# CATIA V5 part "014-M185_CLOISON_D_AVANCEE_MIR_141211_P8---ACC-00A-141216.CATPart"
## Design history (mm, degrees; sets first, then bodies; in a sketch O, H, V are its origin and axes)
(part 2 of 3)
    Fillet35: radius 8, on edge [face of Offset41 | face of Offset41]
    Fillet36: radius 10, on edge [face of Extrude1 from Sketch2.L1 | face of Extrude1 from Sketch2.L2]
    Sweep46: type Segment, GuideCrv edge of Sweep24, GuideSurf Sweep24, Length1 33, Length2 1, Angle 5
    Sweep47: type Segment, GuideCrv edge of Sweep28, GuideSurf Sweep28, Length1 33, Length2 1, Angle 5
    Offset42: Offset Sweep47, Length 2
    Offset43: Offset Sweep46, Length 0.01
  Set8 "RAD"
    Fillet37: radius 5, on edge [face of Chamfer3 | face of Sweep60]
    FaceFillet2: ConicRatio 0.5, Face1 face of Chamfer3, Face2 face of Offset78, Radius 10
    Fillet38: radius 5, on edge [face of Sweep63 | face of Sweep77]; edge [face of Offset78 | face of Sweep63]; edge [face of Sweep76 | face of Sweep77]
    Fillet39: radius 5, on edge [face of Sweep76 | face of Sweep51]
    Fillet40: radius 5, on edge [face of Sweep51 | face of Sweep75]; edge [face of Sweep78 | face of Sweep75]; edge [face of Sweep70 | face of Sweep69]; edge [face of Sweep71 | face of Sweep70]
    Fillet41: radius 5, on edge [face of Sweep48 | face of Sweep49]
    Fillet42: radius 50, on edge [face of Sweep49 | face of Chamfer2]
    Fillet43: radius 20, on edge [face of Chamfer2 | face of Sweep50]
    Fillet44: radius 5, on edge [face of Sweep50 | face of Sweep83]
    Fillet45: radius 5, on edge [face of Sweep82 | face of Sweep83]
    Fillet46: radius 5, on edge [face of Sweep82 | face of Offset76]; edge [face of Sweep81 | face of Offset76]
    Fillet47: radius 5, on edge [face of Sweep58 | face of Sweep73]
    Fillet48: radius 5, on edge [face of Sweep59 | face of Sweep58]; edge [face of Offset63 | face of Sweep59]
    Fillet49: radius 5, on edge [face of Offset63 | face of Sweep66]; edge [face of Sweep80 | face of Sweep66]; edge [face of Sweep80 | face of Sweep68]
    Fillet50: radius 10, on edge [face of Sweep68 | face of Sweep67]
    Fillet51: radius 3, on edge [face of Sweep44 | face of Offset39]
  Set9 "LIMITS HARD"
    Offset44: Offset DatumSurface46, Length 10
    Intersect11: ToIntersect1 Extrapol167, ToIntersect2 Extrapol166
    CurvePar6: Offset Intersect11, Support Extrapol166, Offset2 0, Offset1 16
    Intersect12: ToIntersect1 DatumSurface26, ToIntersect2 DatumSurface27
    Extrapol166: ToExtrapol edge of DatumSurface27, Support DatumSurface27, Length 60
    CurvePar7: Offset Intersect12, Support Extrapol166, Offset2 0, Offset1 25
    Extrapol167: ToExtrapol edge of DatumSurface37, Support DatumSurface37, Length 60
    Intersect13: ToIntersect1 Extrapol166, ToIntersect2 DatumSurface28
    CurvePar8: Offset Intersect13, Support Extrapol166, Offset2 0, Offset1 51.5
    Offset45: Offset DatumSurface1, Length 10
    Intersect14: ToIntersect1 Offset45, ToIntersect2 Extrapol218
    Point1: type OnCurve, Support Intersect14, Ratio 0.2
    CurvePar9: Offset edge of DatumSurface34, Support Extrapol218, Offset2 0, Offset1 50, PassingPoint Point1
    CurvePar10: Offset CurvePar9, Support Extrapol218, Offset2 0, Offset1 0.5
    Sweep48: type Segment, GuideCrv CurvePar8, Length1 20, Length2 20, Angle 3, DraftDirection Line1
    Sweep49: type Segment, GuideCrv CurvePar6, Length1 20, Length2 20, Angle 3, DraftDirection Line1
    Sweep50: type Segment, GuideCrv CurvePar7, Length1 20, Length2 20, Angle 3, DraftDirection Line1
    Sweep51: type Segment, GuideCrv CurvePar10, Length1 20, Length2 20, Angle 3, DraftDirection Line1
    MultiExtract56: ListOfMultiExtractConstraints MultiExtractConstraint face of DatumSurface2
    StUntrimFeature30 "CATStUntrimFeatureName": SpecToUntrim MultiExtract56
    Offset46: Offset StUntrimFeature30, Length 4.5
    Offset47: Offset Offset46, Length 10
    MultiExtract57: ListOfMultiExtractConstraints MultiExtractConstraint face of DatumSurface2
    MultiExtract58: ListOfMultiExtractConstraints MultiExtractConstraint face of DatumSurface2
    MultiExtract59: ListOfMultiExtractConstraints MultiExtractConstraint face of DatumSurface2
    MultiExtract60: ListOfMultiExtractConstraints MultiExtractConstraint face of DatumSurface2
    StUntrimFeature31 "CATStUntrimFeatureName": SpecToUntrim MultiExtract58
    Extrapol168: ToExtrapol edge of StUntrimFeature31, Support StUntrimFeature31, Length 30
    StUntrimFeature32 "CATStUntrimFeatureName": SpecToUntrim MultiExtract57
    Extrapol169: ToExtrapol edge of StUntrimFeature32, Support StUntrimFeature32, Length 30
    Intersect15: ToIntersect1 Extrapol168, ToIntersect2 Extrapol217
    Intersect16: ToIntersect1 Extrapol169, ToIntersect2 Extrapol217
    StUntrimFeature33 "CATStUntrimFeatureName": SpecToUntrim MultiExtract59
    Extrapol170: ToExtrapol edge of StUntrimFeature33, Support StUntrimFeature33, Length 30
    Offset48: Offset Extrapol170, Length 10
    Intersect17: ToIntersect1 Offset48, ToIntersect2 Extrapol211
    StUntrimFeature34 "CATStUntrimFeatureName": SpecToUntrim MultiExtract60
    Extrapol171: ToExtrapol edge of StUntrimFeature34, Support StUntrimFeature34, Length 30
    Offset49: Offset Extrapol171, Length 10
    Intersect18: ToIntersect1 Offset49, ToIntersect2 Extrapol211
    Sweep52: type Segment, GuideCrv Intersect16, Length1 30, Length2 20, Angle 3, DraftDirection Line1
    Sweep53: type Segment, GuideCrv Intersect15, Length1 30, Length2 20, Angle 3, DraftDirection Line1
    Trim61: Trimmed (Offset57; Offset56)
    Extrapol172: ToExtrapol edge of Offset56, Support Trim61, Length 30
    Trim62: Trimmed (Sweep48; Sweep49)
    Trim63: Trimmed (Trim62; Sweep50)
    Sweep54: type Segment, GuideCrv Intersect17, Length1 30, Length2 20, Angle 3, DraftDirection Line1
    Sweep55: type Segment, GuideCrv Intersect18, Length1 30, Length2 20, Angle 3, DraftDirection Line1
    Trim64: Trimmed (Sweep54; Sweep55)
    MultiExtract61: ListOfMultiExtractConstraints MultiExtractConstraint face of DatumSurface2
    StUntrimFeature35 "CATStUntrimFeatureName": SpecToUntrim MultiExtract61
    Extrapol173: ToExtrapol edge of StUntrimFeature35, Support StUntrimFeature35, Length 30
    Offset50: Offset Extrapol173, Length 10
    Extrapol174: ToExtrapol edge of Offset47, Support Offset47, Length 30
    Intersect19: ToIntersect1 Extrapol174, ToIntersect2 Extrapol211
    Intersect20: ToIntersect1 Offset50, ToIntersect2 Extrapol211
    Sweep56: type Segment, GuideCrv Intersect19, Length1 30, Length2 20, Angle 3, DraftDirection Line1
    Sweep57: type Segment, GuideCrv Intersect20, Length1 30, Length2 20, Angle 3, DraftDirection Line1
    Trim65: Trimmed (Sweep57; Trim64)
    Trim66: Trimmed (Sweep56; Extrapol172)
    Trim67: Trimmed (Trim66; Trim65)
    MultiExtract62: ListOfMultiExtractConstraints MultiExtractConstraint face of DatumSurface3
    StUntrimFeature36 "CATStUntrimFeatureName": SpecToUntrim MultiExtract62
    Extrapol175: ToExtrapol edge of StUntrimFeature36, Support StUntrimFeature36, Length 30
    Offset51: Offset Extrapol175, Length 10
    Intersect21: ToIntersect1 Offset51, ToIntersect2 DatumSurface25
    Sweep58: type Segment, GuideCrv Intersect21, Length1 30, Length2 20, Angle 3, DraftDirection Line1
    Extrapol176: ToExtrapol edge of Sweep58, Support Sweep58, Length 50
    Extrapol177: ToExtrapol edge of Sweep58, Support Extrapol176, Length 20
    MultiExtract63: ListOfMultiExtractConstraints MultiExtractConstraint face of DatumSurface5
    StUntrimFeature37 "CATStUntrimFeatureName": SpecToUntrim MultiExtract63
    Extrapol178: ToExtrapol edge of StUntrimFeature37, Support StUntrimFeature37, Length 20
    Offset52: Offset Extrapol178, Length 10
    Intersect22: ToIntersect1 Offset52, ToIntersect2 Extrapol225
    Sweep59: type Segment, GuideCrv Intersect22, Length1 30, Length2 20, Angle 3, DraftDirection Line1
    Trim68: Trimmed (Extrapol177; Sweep59)
    MultiExtract64: ListOfMultiExtractConstraints MultiExtractConstraint face of DatumSurface6
    MultiExtract65: ListOfMultiExtractConstraints MultiExtractConstraint face of DatumSurface6
    StUntrimFeature38 "CATStUntrimFeatureName": SpecToUntrim MultiExtract64
    Extrapol179: ToExtrapol edge of StUntrimFeature38, Support StUntrimFeature38, Length 30
    StUntrimFeature39 "CATStUntrimFeatureName": SpecToUntrim MultiExtract65
    Extrapol180: ToExtrapol edge of StUntrimFeature39, Support StUntrimFeature39, Length 30
    Offset53: Offset Extrapol180, Length 10
    Offset54: Offset Extrapol179, Length 12
    Intersect23: ToIntersect1 Offset54, ToIntersect2 Extrapol217
    Intersect24: ToIntersect1 Offset53, ToIntersect2 Extrapol217
    Sweep60: type Segment, GuideCrv Intersect23, Length1 30, Length2 20, Angle 3, DraftDirection Line1
    Sweep61: type Segment, GuideCrv Intersect24, Length1 30, Length2 20, Angle 3, DraftDirection Line1
    Intersect25: ToIntersect1 Sweep60, ToIntersect2 Sweep61
    Sweep62: type Segment, GuideCrv Intersect25, GuideSurf Sweep61, Length1 30, Length2 20, Angle 3
    Offset55: Offset Sweep62, Length 0.5
    Trim69: Trimmed (Sweep60; Offset55)
    Trim70: Trimmed (Trim67; Trim69)
    Extrapol181: ToExtrapol edge of Offset55, Support Trim70, Length 50
    MultiExtract66: ListOfMultiExtractConstraints MultiExtractConstraint face of DatumSurface6
    MultiExtract67: ListOfMultiExtractConstraints MultiExtractConstraint face of DatumSurface6
    MultiExtract68: ListOfMultiExtractConstraints MultiExtractConstraint face of DatumSurface1
    StUntrimFeature40 "CATStUntrimFeatureName": SpecToUntrim MultiExtract68
    Split60: ToCut StUntrimFeature40, Cutting edge of DatumSurface1
    Split61: ToCut StUntrimFeature40, Cutting edge of Split60
    MultiExtract69: ListOfMultiExtractConstraints MultiExtractConstraint edge of Split60
    Intersect26: ToIntersect1 MultiExtract69, ToIntersect2 Extrapol217
    CurvePar11: Offset edge of DatumSurface30, Support Extrapol217, Offset2 0, Offset1 0.5, PassingPoint Intersect26
    CurvePar12: Offset CurvePar11, Support Extrapol217, Offset2 0, Offset1 16
    Sweep63: type Segment, GuideCrv CurvePar12, Length1 30, Length2 20, Angle 3, DraftDirection Line1
    Extrapol182: ToExtrapol edge of Sweep63, Support Sweep63, Length 50
    Trim71: Trimmed (Trim85; Extrapol182)
    MultiExtract70: ListOfMultiExtractConstraints MultiExtractConstraint edge of MultiExtract66
    Extrude2: Element1 MultiExtract70, Lim1 59, Lim2 75, Direction Line1
    Intersect27: ToIntersect1 Extrude2, ToIntersect2 Extrapol217
    Line11: type PtPt, FirstPoint vertex of Intersect27, SecondPoint vertex of Intersect27, Start 24, End 30
    Sweep64: type Segment, GuideCrv Line11, Length1 30, Length2 20, Angle 3, DraftDirection Line1
    Trim72: Trimmed (Trim71; Offset58)
    Trim73: Trimmed (Trim72; Extrapol181)
    Offset56: Offset Sweep52, Length 12
    Offset57: Offset Sweep53, Length 10
    Offset58: Offset Sweep64, Length 20
    MultiExtract71: ListOfMultiExtractConstraints MultiExtractConstraint face of DatumSurface5
    MultiExtract72: ListOfMultiExtractConstraints MultiExtractConstraint face of DatumSurface5
    StUntrimFeature41 "CATStUntrimFeatureName": SpecToUntrim MultiExtract71
    Extrapol183: ToExtrapol edge of StUntrimFeature41, Support StUntrimFeature41, Length 50
    Offset59: Offset Extrapol183, Length 16.5
    StUntrimFeature42 "CATStUntrimFeatureName": SpecToUntrim MultiExtract72
    Extrapol184: ToExtrapol edge of StUntrimFeature42, Support StUntrimFeature42, Length 50
    Offset60: Offset Extrapol184, Length 10
    Intersect28: ToIntersect1 Offset59, ToIntersect2 Extrapol230
    Intersect29: ToIntersect1 Offset60, ToIntersect2 Extrapol225
    Sweep65: type Segment, GuideCrv Intersect29, Length1 30, Length2 20, Angle 3, DraftDirection Line1
    Sweep66: type Segment, GuideCrv Intersect28, Length1 30, Length2 20, Angle 3, DraftDirection Line1
    Extrapol185: ToExtrapol edge of Sweep66, Support Sweep66, Length 50
    Trim74: Trimmed (Offset63; Extrapol185)
    Trim75: Trimmed (Trim68; Trim74)
    MultiExtract73: ListOfMultiExtractConstraints MultiExtractConstraint face of DatumSurface7
    MultiExtract74: ListOfMultiExtractConstraints MultiExtractConstraint face of DatumSurface7
    StUntrimFeature43 "CATStUntrimFeatureName": SpecToUntrim MultiExtract74
    Extrapol186: ToExtrapol edge of StUntrimFeature43, Support StUntrimFeature43, Length 50
    Offset61: Offset Extrapol186, Length 12
    StUntrimFeature44 "CATStUntrimFeatureName": SpecToUntrim MultiExtract73
    Extrapol187: ToExtrapol edge of StUntrimFeature44, Support StUntrimFeature44, Length 50
    Offset62: Offset Extrapol187, Length 10
    Intersect30: ToIntersect1 Offset62, ToIntersect2 Extrapol211
    Intersect31: ToIntersect1 Offset61, ToIntersect2 Extrapol230
    Sweep67: type Segment, GuideCrv Intersect30, Length1 30, Length2 20, Angle 3, DraftDirection Line1
    Sweep68: type Segment, GuideCrv Intersect31, Length1 30, Length2 20, Angle 3, DraftDirection Line1
    Extrapol188: ToExtrapol edge of Sweep68, Support Sweep68, Length 50
    Trim76: Trimmed (Extrapol188; Sweep67)
    Trim77: Trimmed (Trim76; Trim73)
    Offset63: Offset Sweep65, Length 48
    MultiExtract75: ListOfMultiExtractConstraints MultiExtractConstraint face of DatumSurface9
    MultiExtract76: ListOfMultiExtractConstraints MultiExtractConstraint face of DatumSurface9
    StUntrimFeature45 "CATStUntrimFeatureName": SpecToUntrim MultiExtract75
    Extrapol189: ToExtrapol edge of StUntrimFeature45, Support StUntrimFeature45, Length 50
    StUntrimFeature46 "CATStUntrimFeatureName": SpecToUntrim MultiExtract76
    Extrapol190: ToExtrapol edge of StUntrimFeature46, Support StUntrimFeature46, Length 50
    Offset64: Offset Extrapol189, Length 10
    Offset65: Offset Extrapol190, Length 12
    Intersect32: ToIntersect1 Offset64, ToIntersect2 Offset85
    Intersect33: ToIntersect1 Offset65, ToIntersect2 Offset85
    Sweep69: type Segment, GuideCrv Intersect32, Length1 30, Length2 50, Angle 3, DraftDirection Line1
    Sweep70: type Segment, GuideCrv Intersect33, Length1 30, Length2 50, Angle 3, DraftDirection Line1
    Trim78: Trimmed (Sweep69; Sweep70)
    MultiExtract77: ListOfMultiExtractConstraints MultiExtractConstraint face of DatumSurface4
    MultiExtract78: ListOfMultiExtractConstraints MultiExtractConstraint face of DatumSurface4
    StUntrimFeature47 "CATStUntrimFeatureName": SpecToUntrim MultiExtract78
    Extrapol191: ToExtrapol edge of StUntrimFeature47, Support StUntrimFeature47, Length 50
    Offset66: Offset Extrapol191, Length 10
    StUntrimFeature48 "CATStUntrimFeatureName": SpecToUntrim MultiExtract77
    Extrapol192: ToExtrapol edge of StUntrimFeature48, Support StUntrimFeature48, Length 50
    Offset67: Offset Extrapol192, Length 2
    Intersect34: ToIntersect1 Offset67, ToIntersect2 Extrapol213
    Intersect35: ToIntersect1 Offset66, ToIntersect2 Extrapol213
    Sweep71: type Segment, GuideCrv Intersect35, Length1 30, Length2 50, Angle 3, DraftDirection Line1
    Sweep72: type Segment, GuideCrv Intersect34, Length1 30, Length2 50, Angle 0.5, DraftDirection Line1
    Trim79: Trimmed (Sweep72; Sweep71)
    Trim80: Trimmed (Trim63; Trim79)
    Trim81: Trimmed (Trim78; Trim80)
    MultiExtract79: ListOfMultiExtractConstraints MultiExtractConstraint face of DatumSurface4
    MultiExtract80: ListOfMultiExtractConstraints MultiExtractConstraint face of DatumSurface4
    StUntrimFeature49 "CATStUntrimFeatureName": SpecToUntrim MultiExtract80
    Extrapol193: ToExtrapol edge of StUntrimFeature49, Support StUntrimFeature49, Length 50
    StUntrimFeature50 "CATStUntrimFeatureName": SpecToUntrim MultiExtract79
    Offset68: Offset Extrapol193, Length 2
    Extrapol194: ToExtrapol edge of StUntrimFeature50, Support StUntrimFeature50, Length 50
    Offset69: Offset Extrapol194, Length 11
    Intersect36: ToIntersect1 Extrapol229, ToIntersect2 Offset69
    Intersect37: ToIntersect1 Extrapol229, ToIntersect2 Offset68
    Sweep73: type Segment, GuideCrv Intersect36, Length1 30, Length2 50, Angle 3, DraftDirection Line1
    Sweep74: type Segment, GuideCrv Intersect37, Length1 30, Length2 50, Angle 0.5, DraftDirection Line1
    Trim82: Trimmed (Sweep73; Sweep74)
    Trim83: Trimmed (Trim82; Trim75)
    MultiExtract81: ListOfMultiExtractConstraints MultiExtractConstraint face of DatumSurface10
    MultiExtract82: ListOfMultiExtractConstraints MultiExtractConstraint face of DatumSurface10
    StUntrimFeature51 "CATStUntrimFeatureName": SpecToUntrim MultiExtract82
    Extrapol195: ToExtrapol edge of StUntrimFeature51, Support StUntrimFeature51, Length 120
    Offset70: Offset Extrapol195, Length 10.5
    StUntrimFeature52 "CATStUntrimFeatureName": SpecToUntrim MultiExtract81
    Extrapol196: ToExtrapol edge of StUntrimFeature52, Support StUntrimFeature52, Length 35
    Offset71: Offset Extrapol196, Length 10.5
    MultiExtract83: ListOfMultiExtractConstraints MultiExtractConstraint face of DatumSurface10
    StUntrimFeature53 "CATStUntrimFeatureName": SpecToUntrim MultiExtract83
    Extrapol197: ToExtrapol edge of StUntrimFeature53, Support StUntrimFeature53, Length 35
    Offset72: Offset Extrapol197, Length 11.5
    Intersect38: ToIntersect1 Extrapol218, ToIntersect2 Offset71
    Intersect39: ToIntersect1 Offset70, ToIntersect2 Extrapol218
    Intersect40: ToIntersect1 Offset72, ToIntersect2 Extrapol218
    Sweep75: type Segment, GuideCrv Intersect39, Length1 30, Length2 50, Angle 3, DraftDirection Line1
    Sweep76: type Segment, GuideCrv Intersect38, Length1 30, Length2 50, Angle 3, DraftDirection Line1
    Sweep77: type Segment, GuideCrv Intersect40, Length1 30, Length2 50, Angle 3, DraftDirection Line1
    Trim84: Trimmed (Sweep77; Sweep76)
    Trim85: Trimmed (Sweep51; Trim84)
    Extrapol198: ToExtrapol edge of Sweep75, Support Sweep75, Length 35
    Trim86: Trimmed (Trim77; Extrapol198)
    DatumSurface21
    StUntrimFeature54 "CATStUntrimFeatureName": SpecToUntrim DatumSurface21
    Extrapol199: ToExtrapol edge of StUntrimFeature54, Support StUntrimFeature54, Length 35
    Intersect41: ToIntersect1 Extrapol199, ToIntersect2 Offset85
    Sweep78: type Segment, GuideCrv Intersect41, Length1 30, Length2 50, Angle 3, DraftDirection Line1
    Trim87: Trimmed (Trim86; Sweep78)
    MultiExtract84: ListOfMultiExtractConstraints MultiExtractConstraint edge of DatumSurface11
    MultiExtract85: ListOfMultiExtractConstraints MultiExtractConstraint edge of DatumSurface11
    Extrude3: Element1 MultiExtract84, Lim1 59, Lim2 75, Direction (1, 0, 0)
    Extrude4: Element1 MultiExtract85, Lim1 59, Lim2 75, Direction (1, 0, 0)
    Join14: Elements (Extrude3; Extrude4)
    Offset73: Offset Join14, Length 10
    MultiExtract86: ListOfMultiExtractConstraints MultiExtractConstraint face of DatumSurface13
    StUntrimFeature55 "CATStUntrimFeatureName": SpecToUntrim MultiExtract86
    Extrapol200: ToExtrapol edge of StUntrimFeature55, Support StUntrimFeature55, Length 50
    Offset74: Offset Extrapol200, Length 10
    Intersect42: ToIntersect1 Offset74, ToIntersect2 Extrapol217
    Sweep79: type Segment, GuideCrv Intersect42, Length1 30, Length2 50, Angle 3, DraftDirection Line1
    CurvePar13: Offset edge of Sweep79, Support Sweep79, Offset2 0, Offset1 30
    Split62: ToCut Sweep79, Cutting CurvePar13
    Trim88: Trimmed (Split62; Trim87)
    MultiExtract87: ListOfMultiExtractConstraints MultiExtractConstraint face of DatumSurface14
    StUntrimFeature56 "CATStUntrimFeatureName": SpecToUntrim MultiExtract87
    Extrapol201: ToExtrapol edge of StUntrimFeature56, Support StUntrimFeature56, Length 50
    Offset75: Offset Extrapol201, Length 10
    Intersect43: ToIntersect1 Extrapol230, ToIntersect2 Offset75
    Sweep80: type Segment, GuideCrv Intersect43, Length1 30, Length2 50, Angle 3, DraftDirection Line1
    Trim89: Trimmed (Trim88; Sweep80)
    Trim90: Trimmed (Trim83; Trim89)
    DatumSurface22 to DatumSurface24
    StUntrimFeature57 "CATStUntrimFeatureName": SpecToUntrim DatumSurface22
    Extrapol202: ToExtrapol edge of StUntrimFeature57, Support StUntrimFeature57, Length 50
    StUntrimFeature58 "CATStUntrimFeatureName": SpecToUntrim DatumSurface23
    Extrapol203: ToExtrapol edge of StUntrimFeature58, Support StUntrimFeature58, Length 50
    StUntrimFeature59 "CATStUntrimFeatureName": SpecToUntrim DatumSurface24
    Extrapol204: ToExtrapol edge of StUntrimFeature59, Support StUntrimFeature59, Length 50
    Offset76: Offset Sweep74, Length 20
    Intersect44: ToIntersect1 Extrapol202, ToIntersect2 Extrapol211
    Intersect45: ToIntersect1 Extrapol211, ToIntersect2 Extrapol204
    Intersect46: ToIntersect1 Offset77, ToIntersect2 Extrapol211
    Sweep81: type Segment, GuideCrv Intersect44, Length1 30, Length2 50, Angle 3, DraftDirection Line1
    Sweep82: type Segment, GuideCrv Intersect46, Length1 30, Length2 50, Angle 3, DraftDirection Line1
    Sweep83: type Segment, GuideCrv Intersect45, Length1 30, Length2 50, Angle 3, DraftDirection Line1
    Trim91: Trimmed (Sweep83; Sweep82)
    Trim92: Trimmed (Offset76; Trim91)
    Trim93: Trimmed (Trim90; Sweep81)
    Trim94: Trimmed (Trim92; Trim93)
    Trim95: Trimmed (Trim81; Trim94)
    Chamfer2: length 47, second length 32, on edge [face of Sweep49 | face of Sweep50]
    Offset77: Offset Extrapol203, Length 1
    Sweep84: type Segment, GuideCrv Intersect47, GuideSurf Sweep79, Length1 30, Length2 20, Angle 30
    Extrapol205: ToExtrapol edge of Offset78, Support Offset78, Length 15
    Trim96: Trimmed (Chamfer2; Extrapol205)
    Chamfer3: length 29, second length 21, on edge [face of Offset55 | face of Sweep60]
    Offset78: Offset Sweep84, Length 2
    Extrapol206: ToExtrapol edge of Sweep48, Support Chamfer3, Length 17
    Extrapol207: ToExtrapol edge of Sweep56, Support Sweep56, Length 80
    Extrapol208: ToExtrapol edge of Sweep55, Support Sweep55, Length 80
    Extrapol209: ToExtrapol edge of Offset56, Support Offset56, Length 80
    Extrapol210: ToExtrapol edge of Offset57, Support Offset57, Length 80
    Offset79: Offset Extrapol209, Length 15
    Offset80: Offset Extrapol210, Length 15
    Offset81: Offset Extrapol207, Length 15
    Offset82: Offset Extrapol208, Length 15
    Trim97: Trimmed (Offset81; Offset79)
    Trim98: Trimmed (Trim97; Offset80)
    Trim99: Trimmed (Trim98; Offset82)
  Set10 "A FACE HARD MATERIAL"
    DatumSurface25 to DatumSurface45
    Extrapol211: ToExtrapol edge of DatumSurface25, Support DatumSurface25, Length 100
    Extrapol212: ToExtrapol edge of DatumSurface26, Support DatumSurface26, Length 40
    Extrapol213: ToExtrapol edge of DatumSurface27, Support DatumSurface27, Length 130
    Extrapol214: ToExtrapol edge of DatumSurface28, Support DatumSurface28, Length 80
    Extrapol215: ToExtrapol edge of DatumSurface29, Support DatumSurface29, Length 150
    Trim100: Trimmed (Offset85; Extrapol214)
    Trim101: Trimmed (Extrapol211; Extrapol212)
    Trim102: Trimmed (Extrapol213; Trim101)
    Trim103: Trimmed (Trim100; Trim102)
    Extrapol216: ToExtrapol edge of DatumSurface33, Support DatumSurface33, Length 60
    Extrapol217: ToExtrapol edge of DatumSurface30, Support DatumSurface30, Length 30
    Extrapol218: ToExtrapol edge of DatumSurface34, Support DatumSurface34, Length 30
    Extrapol219: ToExtrapol edge of DatumSurface35, Support DatumSurface35, Length 30
    Extrapol220: ToExtrapol edge of DatumSurface32, Support DatumSurface32, Length 30
    Extrapol221: ToExtrapol edge of DatumSurface31, Support DatumSurface31, Length 30
    Extrapol222: ToExtrapol edge of DatumSurface36, Support DatumSurface36, Length 50
    Extrapol223: ToExtrapol edge of DatumSurface37, Support DatumSurface37, Length 30
    Sweep85: type Segment, GuideCrv edge of DatumSurface37, GuideSurf Trim110, Length1 20, Length2 20, Angle 90
    Extrapol224: ToExtrapol edge of Sweep85, Support Sweep85, Length 120
    Offset83: Offset Extrapol224, Length 29
    Trim104: Trimmed (Extrapol217; Extrapol216)
    Trim105: Trimmed (Trim104; Extrapol218)
    Trim106: Trimmed (Extrapol222; Extrapol219)
    Trim107: Trimmed (Extrapol221; Extrapol220)
    Trim108: Trimmed (Trim106; Trim107)
    Trim109: Trimmed (Trim108; Extrapol223)
    Trim110: Trimmed (Trim109; Trim105)
    Trim111: Trimmed (Trim110; Offset83)
    Trim112: Trimmed (Trim111; Trim103)
    Extrapol225: ToExtrapol edge of DatumSurface39, Support DatumSurface39, Length 120
    Extrapol226: ToExtrapol edge of DatumSurface38, Support DatumSurface38, Length 120
    Trim113: Trimmed (Extrapol225; Extrapol226)
    Trim114: Trimmed (Trim112; Trim113)
    Extrapol227: ToExtrapol edge of DatumSurface40, Support DatumSurface40, Length 120
    Extrapol228: ToExtrapol edge of Offset86, Support Offset86, Length 120
    Extrapol229: ToExtrapol edge of DatumSurface41, Support DatumSurface41, Length 120
    Trim115: Trimmed (DatumSurface43; Extrapol227)
    Trim116: Trimmed (Extrapol228; Trim115)
    Trim117: Trimmed (Trim116; Extrapol229)
    Trim118: Trimmed (Trim114; Trim117)
    Extrapol230: ToExtrapol edge of DatumSurface45, Support DatumSurface45, Length 30
    Extrapol231: ToExtrapol edge of DatumSurface44, Support DatumSurface44, Length 30
    Sweep86: type Segment, GuideCrv edge of DatumSurface45, GuideSurf Extrapol230, Length1 20, Length2 20, Angle 90
    Offset84: Offset Sweep86, Length -52
    Extrapol232: ToExtrapol edge of DatumSurface45, Support Extrapol230, Length 60
    Extrapol233: ToExtrapol edge of DatumSurface44, Support Extrapol231, Length 60
    Trim119: Trimmed (Extrapol232; Extrapol233)
    Trim120: Trimmed (Offset84; Trim119)
    Trim121: Trimmed (Trim118; Trim120)
    Offset85: Offset Extrapol215, Length 0.025
    Fillet52: radius 11.8, on edge [face of DatumSurface35 | face of DatumSurface32]
    Fillet53: radius 11.8, on edge [face of DatumSurface36 | face of DatumSurface37]
    Fillet54: radius 30, on edge [face of DatumSurface34 | face of DatumSurface33]
    Fillet55: radius 30, on edge [face of DatumSurface30 | face of DatumSurface33]
    Fillet56: radius 25, on edge [face of DatumSurface25 | face of DatumSurface26]
    Fillet57: radius 25, on edge [face of DatumSurface27 | face of DatumSurface26]
    Fillet58: radius 7.5, on edge [face of DatumSurface35 | face of DatumSurface36]
    Fillet59: radius 8.2, on edge [face of DatumSurface32 | face of DatumSurface31]
    Fillet60: radius 8.2, on edge [face of DatumSurface30 | face of DatumSurface37]
    Fillet61: radius 6, on edge [face of DatumSurface27 | face of DatumSurface28]
    Fillet62: radius 11.8, on edge [face of DatumSurface27 | face of DatumSurface37]
    Fillet63: radius 6.8, on edge [face of Offset85 | face of DatumSurface35]
    Fillet64: radius 5, on edge [face of DatumSurface45 | face of DatumSurface44]
    Fillet65: radius 6.8, on edge [face of DatumSurface44 | face of DatumSurface25]
    Fillet66: radius 1, on edge [face of DatumSurface25 | face of DatumSurface38]
    Fillet67: radius 5, on edge [face of DatumSurface38 | face of DatumSurface39]
    Fillet68: radius 8.2, on edge [face of DatumSurface43 | face of Offset86]
    Fillet69: radius 8.2, on edge [face of DatumSurface40 | face of DatumSurface41]
    Fillet70: radius 3.2, on edge [face of DatumSurface41 | face of Offset86]
    Fillet71: radius 2.8, on edge [face of DatumSurface25 | face of Offset86]
    Intersect47: ToIntersect1 Sweep79, ToIntersect2 Sweep63
    Fillet72: radius 10, on edge [face of DatumSurface25 | face of Offset83]
    Fillet73: radius 10, on edge [face of DatumSurface30 | face of Offset83]
    Offset86: Offset DatumSurface42, Length 3
  Set11 "STP"
    Offset87: Offset Fillet73, Length 0.9
    MultiExtract88: ListOfMultiExtractConstraints MultiExtractConstraint face of Fillet85
    MultiExtract89: ListOfMultiExtractConstraints MultiExtractConstraint face of Split72
    MultiExtract90: ListOfMultiExtractConstraints MultiExtractConstraint face of Split72
    Extrapol234: ToExtrapol edge of MultiExtract88, Support MultiExtract88, Length 1
    Offset88: Offset Extrapol234, Length 2
    Split63: ToCut Offset88, Cutting edge [face of Offset88 | face of Offset88]
    Extrapol235: ToExtrapol edge of Split63, Support Split63, Length 10
    Extrapol236: ToExtrapol edge of MultiExtract90, Support MultiExtract90, Length 4
    Offset89: Offset Extrapol236, Length 2
    Sweep87: type Segment, GuideCrv edge of Offset89, Length1 3, Length2 3, Angle 45, DraftDirection face of Offset89
    Trim122: Trimmed (Offset89; Sweep87)
    Trim123: Trimmed (Trim122; Extrapol235)
    Split64: ToCut Trim123, Cutting edge [face of Offset89 | face of Offset89]
    Extrapol237: ToExtrapol edge of Split64, Support Split64, Length 8
    Sweep88: type Segment, GuideCrv edge of Split63, GuideSurf Extrapol237, Length1 5, Length2 0, Angle 90
    Sweep89: type Segment, GuideCrv edge of Split64, GuideSurf Extrapol237, Length1 5, Length2 0, Angle 90
    Join15: Elements (Sweep89; Extrapol237; Sweep88)
    Trim124: Trimmed (Join15; Offset87)
    Join16: Elements Fillet50, SubElementsToRemove face of Sweep72
    Split65: ToCut Join16, Cutting edge [face of Sweep73 | face of Fillet47]
    Trim125: Trimmed (Split65; Trim124)
    Extrapol238: ToExtrapol edge of MultiExtract89, Support MultiExtract89, Length 1
    Offset90: Offset Extrapol238, Length 2
    Split66: ToCut Offset90, Cutting edge [face of Offset90 | face of Offset90]
    Extrapol239: ToExtrapol edge of Split66, Support Split66, Length 10
    Trim126: Trimmed (Offset87; Extrapol239)
    Fillet74: radius 5, on edge [face of Sweep74 | face of Sweep81]
    MultiExtract91: ListOfMultiExtractConstraints MultiExtractConstraint face of Sweep48
    Split67: ToCut Fillet74, Cutting edge [face of Fillet41 | face of Sweep49]
    Extrapol240: ToExtrapol edge of MultiExtract91, Support MultiExtract91, Length 10
    Offset91: Offset Extrapol240, Length 0.5
    Extrapol241: ToExtrapol edge of Split67, Support Split67, Length 10
    Trim127: Trimmed (Extrapol241; Offset91)
    Fillet75: radius 5, on edge [face of Offset91 | face of Sweep49]
    Trim128: Trimmed (Fillet75; Trim126)
    Join17: Elements (Trim125; Trim128)
    Fillet76: radius 5, on edge [face of Sweep74 | face of Sweep73]
    Plane10: type OffsetPt, RefPlane face of ThickSurface1, RefPoint vertex [face of ThickSurface2 | face of Split92 | face of ThickSurface2]
    Sketch3 on Plane10, origin (0, 387.0463, 0), H (1, 0, 0), V (0, 0, 1)
      line L1 (-700.2637, 17.0869) -> (-707.1107, 17.0869)
      line L2 (-707.1107, 17.0869) -> (-707.1107, 11.3659)
      line L3 (-707.1107, 11.3659) -> (-700.2637, 11.3659)
      line L4 (-700.2637, 11.3659) -> (-700.2637, 17.0869)
      horizontal: L1 H, L3 H
      vertical: L2 V, L4 V
    Extrude5: Element1 Sketch3, Lim1 59, Lim2 75
    MultiExtract92: ListOfMultiExtractConstraints MultiExtractConstraint face of ThickSurface2
    Trim129: Trimmed (MultiExtract92; Extrude5)
    Plane11: type Tangent, Support face of Solid5, RefPoint vertex [face of Solid5 | face of Solid5 | face of Solid5 | face of Solid5]
    Sketch4 on Plane11, origin (0, 375.7625, 0), H (1, 0, 0), V (0, 0, 1)
      line L1 (-767.8585, 374.9812) -> (-779.3658, 374.9812)
      line L2 (-779.3658, 374.9812) -> (-779.3658, 365.4898)
      line L3 (-779.3658, 365.4898) -> (-767.8585, 365.4898)
      line L4 (-767.8585, 365.4898) -> (-767.8585, 374.9812)
      horizontal: L1 H, L3 H
      vertical: L2 V, L4 V
    Extrude6: Element1 Sketch4, Lim1 59, Lim2 75
    MultiExtract93: ListOfMultiExtractConstraints MultiExtractConstraint face of Solid5
    Trim130: Trimmed (MultiExtract93; Extrude6)
    MultiExtract94: ListOfMultiExtractConstraints MultiExtractConstraint face of Sweep72
    Extrapol242: ToExtrapol edge of MultiExtract94, Support MultiExtract94, Length -20
    Sweep90: type Segment, GuideCrv edge of MultiExtract94, GuideSurf Extrapol242, Length1 5, Length2 0, Angle 90
    Join18: Elements (Sweep90; Extrapol242; Fillet76)
    Offset92: Offset Fillet73, Length 1.8
    MultiExtract95: ListOfMultiExtractConstraints (MultiExtractConstraint face of Split73; MultiExtractConstraint face of Split73)
    Join19: Elements Join18, SubElementsToRemove (face of Sweep69; face of Sweep78; face of Fillet40)
    Split68: ToCut MultiExtract95, Cutting edge [face of Split72 | face of Fillet80]
    Trim131: Trimmed (edge [face of Offset87 | face of Sweep75]; edge of Split68)
    Split69: ToCut Join19, Cutting Trim131
    Split70: ToCut Split68, Cutting edge of Join19
    Trim132: Trimmed (Split69; Split70)
    MultiExtract96: ListOfMultiExtractConstraints (MultiExtractConstraint face of Fillet82; MultiExtractConstraint face of Split74; MultiExtractConstraint face of Fillet83; MultiExtractConstraint face of Split74; MultiExtractConstraint face of Fillet84; MultiExtractConstraint face of Split74; MultiExtractConstraint face of Fillet85; MultiExtractConstraint face of Split74; MultiExtractConstraint face of Fillet86)
    Split71: ToCut Trim132, Cutting MultiExtract96
    Join20: Elements (Split71; MultiExtract96)
  DatumSurface46 "--.------.---.AA37350935.FL.COMP_COND-----------.----0001CAT-NOT IN USE"
  Plane12: type Normal, Curve Line1
Set12 "NEW ENV"
  DatumSurface47 "AU.P84SR-.R1A.9810634680.00.ARMA-PARE-CHO-AV-ASS.----0006CAT"
Body1 (main body)
Body2 "HARD_MATERIAL_ADVANCED"
  Body3
    ThickSurface1: BotOffset 0, Surface Fillet73, TopOffset 1.8
    Split72: SplitPlane Fillet50
    Split73: SplitPlane Fillet51
  Add1: tool Body3
  Split74: SplitPlane Trim99
  Body4 "FIXING-2"
    Solid1: solid without history
    Thickness1: Face face of Solid1, Thickness 20
    Align1: SewingRemoveFace face of Solid1, SplitPlane Sweep72
    RemoveFace1: RemoveFaces (face of Solid1; face of Solid1)
    RemoveFace2: RemoveFaces face of Solid1
    Thickness2: Face face of Solid1, Thickness 1
    Split75: SplitPlane Extrapol47
    Split76: SplitPlane Extrapol48
    Split77: SplitPlane Fillet73
    Thickness3: Face face of Split76, Thickness -0.5
    Thickness4: Face face of Split75, Thickness -2
  Add2: tool Body4
  RemoveFace3: RemoveFaces face of Split72
  Thickness5: Face face of Split72, Thickness -0.5
  Fillet77: radius 5, on edge [face of Split72 | face of Split72]
  Fillet78: radius 1.5, on edge [face of Solid1 | face of ThickSurface1]
  Body5 "FIXING-1"
    Solid2: solid without history
    Thickness6: Face face of Solid2, Thickness 20
    RemoveFace4: RemoveFaces (face of Solid2; face of Solid2)
    Align2: SewingRemoveFace face of Solid2, SplitPlane Sweep74
    Thickness7: Face (face of Solid2; face of Solid2), Thickness -3.5
    Split78: SplitPlane Fillet73
  Add3: tool Body5
  Fillet79: radius 1.5, on edge [face of Solid2 | face of ThickSurface1]
  Fillet80: radius 5, on edge [face of Split73 | face of Split72] (x2)
  Fillet81: radius 3, on edge [face of Split72 | face of Split72]
  Fillet82: radius 5, on edge [face of Split74 | face of Split72]
  Fillet83: radius 25, on edge [face of Split74 | face of Split74]
  Fillet84: radius 25, on edge [face of Split74 | face of Split74]
  Fillet85: radius 25, on edge [face of Split74 | face of Split74]
  Fillet86: radius 5, on edge [face of Split72 | face of Split74]
  Fillet87: radius 5, on edge [face of Split72 | face of Split72]
  Fillet88: radius 5, on edge [face of Split72 | face of Split72]
  Split79: SplitPlane Extrapol147
  Thickness8: Face face of Split79, Thickness 0.4
  Thickness9: Face face of Split79, Thickness -0.4
  Split80: SplitPlane Trim124
  Split81: SplitPlane Trim126
  Draft1: Angle 3, Neutral Offset92, PullDir Line1, SupportToDraft (face of Solid2; face of Solid2; face of Split75)
  Draft2: Angle 3, Neutral face of ThickSurface1, PullDir Line1, SupportToDraft (face of Split79; face of Split79)
  Body6
    Sketch5 on face of ThickSurface1, origin (0, 378.041, 0), H (-1, 0, 0), V (0, 0, 1)
      line L1 (835.034, 55.1759) -> (796.0333, 55.1759)
      line L2 (796.0333, 55.1759) -> (796.0333, 66.75)
      line L3 (796.0333, 66.75) -> (835.034, 66.75)
      line L4 (835.034, 66.75) -> (835.034, 55.1759)
      horizontal: L1 H, L3 H
      vertical: L2 V, L4 V
    Pad1: profile Sketch5, direction (0, 1, 0), up to face of ThickSurface1, opposite side up to face of ThickSurface1
    Draft3: Angle 15, Neutral start face of Pad1, PullDir Line1, SupportToDraft (face of Pad1 from Sketch5.L1; face of Pad1 from Sketch5.L2; face of Pad1 from Sketch5.L3)
    Fillet89: radius 5, on edge [face of Pad1 from Sketch5.L2 | face of Pad1 from Sketch5.L1]; edge [face of Pad1 from Sketch5.L3 | face of Pad1 from Sketch5.L2]
    Fillet90: radius 5, on edge [face of Pad1 from Sketch5.L2 | start face of Pad1]
    Shell1: ExtOffset 0, Face (end face of Pad1; face of Pad1 from Sketch5.L4), IntOffset 1.8
    Thickness10: Face end face of Pad1, Thickness 3
  Trim133: tool Body6, faces to remove end face of Pad1
  Fillet91: radius 2.5, on edge [face of ThickSurface1 | face of Pad1 from Sketch5.L3]
  Fillet92: radius 4.3, on edge [face of ThickSurface1 | face of Shell1]
  Fillet93: radius 1.5, on edge [face of Split79 | face of Split79] (x4)
  Fillet94: radius 0.5, on edge [face of ThickSurface1 | face of Split79]
  Body7 "soft material advanced"
    Solid3: linked copy from another document
    Split82: SplitPlane Fillet36
    Sketch6 on face of Solid3, origin (0, 375.7625, 0), H (-1, 0, 0), V (0, 0, 1)
      line L1 (569.8051, 459.0137) -> (760.1343, 439.068)
      line L2 (760.1343, 439.068) -> (787.1793, 407.9662)
      line L3 (787.1793, 407.9662) -> (773.6568, 380.5832)
      line L4 (773.6568, 380.5832) -> (728.0184, 321.7603)
      line L5 (728.0184, 321.7603) -> (569.8051, 286.5903)
      line L6 (569.8051, 286.5903) -> (523.6584, -224.2788)
      line L7 (523.6584, -224.2788) -> (1197.0264, -207.2798)
      line L8 (1197.0264, -207.2798) -> (1082.0062, 498.2725)
      line L9 (1082.0062, 498.2725) -> (918.0983, 856.6172)
      line L10 (918.0983, 856.6172) -> (511.2509, 744.9617)
      line L11 (511.2509, 744.9617) -> (569.8051, 459.0137)
    Pocket1: profile Sketch6, direction (0, -1, 0), length 400, mirrored extent
  Add4: tool Body7
  Fillet95: radius 8, on edge [face of Split82 | face of Split72]
  Fillet96: radius 10, on edge [face of Split82 | face of Split81]
  Fillet97: radius 8, on edge [face of Split82 | face of Split82]; edge [face of Split81 | face of Split82]
  Fillet98: radius 10, on edge [face of Split82 | face of Split82]; edge [face of Split72 | face of Split82]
